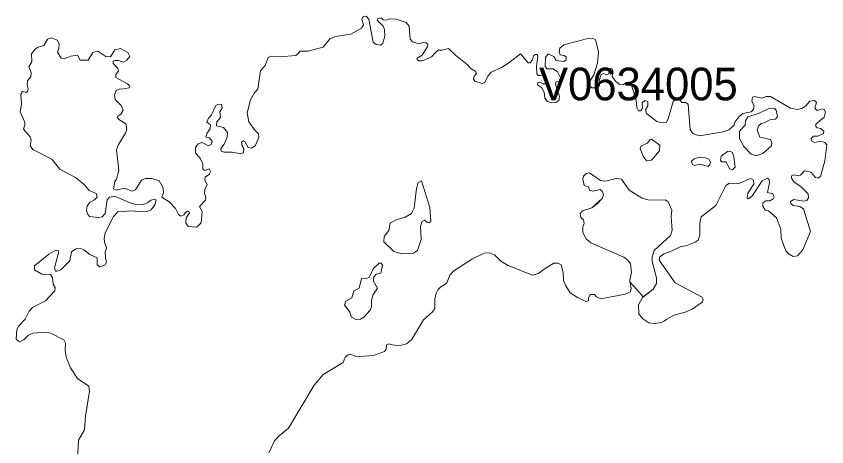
# Model space of a CAD drawing. Extents: x 369010 to 735936, y 6377141 to 6616555.
# Drawn here: x 451878 to 454365, y 6480290 to 6481609 of the extents above; entities that cross this region are included whole.
import ezdxf
from ezdxf.enums import TextEntityAlignment as Align

# ---------------------------------------------------------------- set-up
doc = ezdxf.new("R2010")
doc.units = 0
doc.header["$LTSCALE"] = 40
doc.layers.add('3', color=7, linetype='Continuous', lineweight=13)
doc.layers.add('4', color=7, linetype='Continuous')

msp = doc.modelspace()

# ---------------------------------------------------------------- linework, layer by layer
at = {"layer": '3'}
for points in [[(452404.03, 6481012.12), (452408.33, 6481011.3), (452409.49, 6481006.33), (452399.4, 6480991.44), (452398.4, 6480975.71), (452406.35, 6480964.96), (452432, 6480962.31), (452445.41, 6480976.54), (452448.88, 6481010.97), (452440.77, 6481025.86), (452459.14, 6481045.06), (452459.97, 6481054.99), (452455.83, 6481065.75), (452456.99, 6481078.82), (452463.78, 6481092.56), (452457.49, 6481107.45), (452458.31, 6481115.9), (452471.72, 6481124.83), (452474.04, 6481133.6), (452470.56, 6481141.22), (452456, 6481136.25), (452451.03, 6481141.55), (452451.03, 6481156.94), (452442.26, 6481173.82), (452428.36, 6481189.88), (452428.69, 6481207.09), (452436.47, 6481217.85), (452448.72, 6481222.81), (452467.91, 6481211.72), (452477.35, 6481217.02), (452479.5, 6481225.96), (452471.06, 6481236.22), (452460.3, 6481238.86), (452463.11, 6481250.12), (452473.38, 6481263.86), (452474.87, 6481276.43), (452463.11, 6481284.54), (452468.08, 6481296.46), (452477.18, 6481307.05), (452490.59, 6481335.85), (452498.37, 6481339.66), (452508.63, 6481338.5), (452509.79, 6481328.24), (452503.33, 6481316.32), (452505.15, 6481298.78), (452493.73, 6481286.03), (452492.91, 6481272.96), (452514.42, 6481267.99), (452526.67, 6481252.77), (452525.84, 6481238.2), (452516.74, 6481217.51), (452505.98, 6481204.44), (452507.14, 6481195.67), (452516.24, 6481193.02), (452540.74, 6481192.52), (452567.22, 6481187.56), (452575.99, 6481191.03), (452576.32, 6481203.61), (452571.19, 6481211.72), (452569.7, 6481223.14), (452574.33, 6481227.11), (452579.3, 6481225.13), (452590.39, 6481206.76), (452599.99, 6481204.77), (452611.57, 6481211.72), (452622.99, 6481237.38), (452621.5, 6481248.46), (452609.59, 6481260.71), (452592.37, 6481285.37), (452586.58, 6481313.18), (452597.17, 6481353.06), (452608.92, 6481374.58), (452619.35, 6481385.67), (452627.46, 6481441.61), (452642.19, 6481458.49), (452651.29, 6481482.65), (452660.89, 6481487.12), (452687.7, 6481484.8), (452736.03, 6481488.78), (452743.81, 6481495.23), (452748.11, 6481502.51), (452773.27, 6481502.51), (452819.61, 6481514.76), (452841.95, 6481541.24), (452858.5, 6481547.36), (452905.34, 6481554.65), (452937.78, 6481572.52), (452943.24, 6481582.62), (452938.94, 6481599), (452942.41, 6481608.6), (452952.18, 6481609.43), (452960.29, 6481600.49), (452973.69, 6481530.15), (452982.14, 6481522.37), (452996.2, 6481520.88), (453003.15, 6481527.34), (453008.95, 6481548.03), (453008.12, 6481568.38), (453004.31, 6481579.14), (452985.61, 6481597.84)], [(452985.61, 6481597.84), (452987.43, 6481602.81), (452997.86, 6481604.79), (453004.31, 6481598.34), (453014.57, 6481597.18), (453023.84, 6481600.99), (453044.2, 6481600.16), (453074.82, 6481590.56), (453083.75, 6481579.14), (453086.4, 6481539.59), (453093.68, 6481531.14), (453114.87, 6481525.02), (453126.29, 6481528.99), (453135.89, 6481528.17), (453140.85, 6481523.2), (453140.52, 6481517.08), (453123.97, 6481489.77), (453108.25, 6481480.67), (453108.08, 6481476.36), (453113.55, 6481472.23), (453124.14, 6481472.23), (453152.11, 6481485.3), (453165.18, 6481499.37), (453172.8, 6481505.49), (453185.54, 6481505.16), (453204.57, 6481510.46), (453226.42, 6481489.77), (453262.17, 6481461.8), (453274.42, 6481448.06), (453286.66, 6481441.11), (453290.8, 6481433.83), (453282.86, 6481425.39), (453280.87, 6481416.29), (453285.67, 6481410.49), (453307.85, 6481402.88), (453315.46, 6481406.69), (453325.06, 6481425.88), (453335.49, 6481438.13), (453366.93, 6481452.7), (453389.27, 6481466.93), (453425.69, 6481493.74), (453449.02, 6481466.43), (453455.15, 6481466.43), (453462.1, 6481475.7), (453465.57, 6481488.28), (453470.7, 6481492.58), (453476.83, 6481491.75), (453478.65, 6481486.46), (453474.51, 6481456.83), (453475.17, 6481432.34), (453479.14, 6481427.7), (453485.6, 6481427.37), (453493.21, 6481429.69), (453503.14, 6481423.24), (453506.29, 6481407.84), (453501.32, 6481401.72), (453494.87, 6481402.55), (453484.44, 6481407.02), (453478.32, 6481406.35), (453477.16, 6481399.07), (453489.74, 6481390.63), (453497.51, 6481376.4), (453500.16, 6481358.03), (453507.78, 6481347.77), (453520.52, 6481343.79), (453533.43, 6481344.62), (453542.7, 6481351.57), (453544.52, 6481363.82), (453532.27, 6481400.89), (453534.59, 6481407.84), (453545.01, 6481409.83), (453548.49, 6481420.42), (453538.39, 6481439.29), (453525.48, 6481448.06), (453506.29, 6481448.06), (453501.32, 6481456.5), (453501.65, 6481482.98), (453510.42, 6481494.07), (453527.8, 6481485.63), (453534.26, 6481473.71), (453557.92, 6481470.24), (453565.21, 6481475.7), (453565.21, 6481485.3), (453559.58, 6481489.11), (453546.83, 6481490.6), (453543.86, 6481499.86), (453546.5, 6481511.62), (453558.75, 6481522.04), (453627.93, 6481540.41), (453645.14, 6481541.9), (453655.9, 6481538.43), (453664.34, 6481500.2), (453661.2, 6481465.77), (453650.11, 6481429.36), (453634.55, 6481405.2), (453636.21, 6481397.09), (453644.48, 6481390.3), (453656.89, 6481389.8), (453667.49, 6481395.93), (453668.65, 6481404.04)], [(452102.48, 6481075.35), (452085.77, 6481094.55), (452060.44, 6481115.23), (452012.61, 6481140.89), (451987.29, 6481171.01), (451929.7, 6481200.96), (451921.25, 6481212.38), (451923.9, 6481230.09), (451921.59, 6481240.02), (451900.57, 6481263.03), (451904.54, 6481276.77), (451904.7, 6481284.54), (451890.47, 6481316.32), (451894.28, 6481339.33), (451892.62, 6481370.61), (451897.59, 6481378.38), (451909.5, 6481376.07), (451914.14, 6481381.03), (451915.3, 6481386.33), (451911.49, 6481398.25), (451912.65, 6481412.81), (451923.08, 6481423.24), (451924.73, 6481436.64), (451917.45, 6481454.52), (451926.22, 6481469.58), (451925.39, 6481493.74), (451937.31, 6481508.97), (451946.08, 6481514.76), (451962.63, 6481519.73), (451974.88, 6481538.92), (451986.3, 6481543.06), (452004.34, 6481535.78), (452009.8, 6481524.69), (452009.3, 6481510.13), (452005.5, 6481499.37), (452016.25, 6481480.67), (452025.69, 6481478.35), (452045.55, 6481486.79), (452065.9, 6481489.77), (452074.68, 6481474.87), (452098.84, 6481475.2), (452113.74, 6481498.71), (452128.96, 6481502.51), (452153.29, 6481485.63), (452167.52, 6481484.47), (452180.6, 6481505.99), (452197.81, 6481510.13), (452220.82, 6481497.88), (452226.94, 6481486.46), (452217.34, 6481474.54), (452206.25, 6481468.42), (452192.52, 6481473.38), (452180.93, 6481473.71), (452175.63, 6481471.4), (452175.97, 6481464.12), (452189.7, 6481449.55), (452192.52, 6481440.78), (452184.07, 6481430.85), (452184.41, 6481422.08), (452219.33, 6481402.55), (452225.78, 6481395.93), (452224.62, 6481390.3), (452202.78, 6481385.67), (452195.83, 6481386.83), (452184.74, 6481381.36), (452179.94, 6481367.63), (452181.59, 6481354.22), (452199.96, 6481336.18), (452206.09, 6481321.62), (452199.14, 6481308.71), (452189.87, 6481303.25), (452188.87, 6481298.28), (452196.49, 6481290.67), (452214.53, 6481279.08), (452217.84, 6481261.87), (452213.37, 6481250.45), (452192.02, 6481216.69), (452185.56, 6481200.3), (452192.85, 6481136.58), (452186.06, 6481110.27), (452181.1, 6481102.99), (452176.46, 6481080.31), (452185.4, 6481076.17), (452210.56, 6481082.3), (452234.39, 6481072.7), (452243.99, 6481077.17), (452262.36, 6481106.79), (452274.61, 6481112.09), (452294.63, 6481111.76), (452316.48, 6481104.81), (452329.55, 6481083.46), (452330.71, 6481066.58), (452324.59, 6481054.99), (452347.26, 6481040.09), (452366.96, 6481020.23), (452376.06, 6481001.86), (452383.01, 6480996.73), (452392.11, 6481000.21), (452396.42, 6481007.16), (452404.03, 6481012.12)], [(453668.65, 6481404.04), (453667.16, 6481412.81), (453672.45, 6481430.52), (453679.07, 6481433.5), (453690.49, 6481429.36), (453695.95, 6481432.34), (453698.6, 6481447.73), (453705.39, 6481449.55), (453708.53, 6481442.27), (453706.55, 6481425.06), (453716.64, 6481410.49), (453729.22, 6481399.73), (453739.48, 6481399.07), (453747.43, 6481404.7), (453765.47, 6481398.58), (453780.36, 6481352.23), (453781.85, 6481329.23), (453787.64, 6481319.3), (453794.93, 6481318.97), (453799.56, 6481327.41), (453799.06, 6481343.79), (453806.84, 6481350.75), (453815.94, 6481348.43), (453815.61, 6481334.36), (453809.16, 6481322.78), (453811.81, 6481310.86), (453843.25, 6481287.19), (453859.8, 6481282.89), (453872.55, 6481283.72), (453878.67, 6481295.3), (453893.9, 6481347.77), (453899.69, 6481355.38), (453911.11, 6481358.03), (453920.05, 6481344.62), (453931.13, 6481344.95), (453939.58, 6481339.33), (453946.03, 6481261.04), (453954.14, 6481249.95), (453974, 6481242.67), (454047.48, 6481254.59), (454064.2, 6481261.04), (454080.59, 6481275.61), (454082.9, 6481284.87), (454094.82, 6481301.43), (454107.4, 6481310.86), (454132.72, 6481316.65), (454140.5, 6481324.76), (454142.65, 6481335.52), (454134.87, 6481348.92), (454137.52, 6481361.5), (454144.47, 6481363.82), (454165.16, 6481358.36), (454178.56, 6481363.82), (454192.63, 6481362.99), (454253.54, 6481327.41), (454275.05, 6481323.6), (454290.61, 6481327.74), (454300.87, 6481334.69), (454312.46, 6481349.26), (454327.35, 6481350.75), (454333.48, 6481344.62), (454328.18, 6481327.41), (454333.14, 6481320.95), (454340.43, 6481320.95), (454351.02, 6481325.92), (454356.81, 6481323.93), (454360.62, 6481316.32), (454356.48, 6481300.27), (454331.49, 6481278.75), (454331.49, 6481271.8), (454335.46, 6481266.83), (454346.88, 6481265.68), (454356.15, 6481256.9), (454355.32, 6481249.62), (454337.61, 6481241.51), (454324.21, 6481241.51), (454317.42, 6481234.73), (454317.75, 6481227.44), (454327.35, 6481222.81), (454348.04, 6481226.62), (454359.13, 6481222.81), (454364.92, 6481215.2), (454358.63, 6481166.04), (454345.89, 6481117.88), (454337.45, 6481113.25), (454329.83, 6481114.74), (454315.6, 6481131.62), (454296.57, 6481135.42), (454284.32, 6481122.02), (454278.86, 6481120.53), (454264.29, 6481123.51), (454256.68, 6481120.2), (454256.35, 6481113.25), (454264.29, 6481101.66), (454285.98, 6481086.44), (454307.49, 6481064.59), (454309.31, 6481052.67), (454304.02, 6481044.73), (454294.09, 6481042.74), (454263.8, 6481047.71)], [(454263.8, 6481047.71), (454253.37, 6481041.91), (454254.53, 6481033.97), (454262.64, 6481029.01), (454282.5, 6481026.19), (454293.59, 6481018.91), (454314.94, 6480949.23), (454291.44, 6480893.79), (454274.89, 6480874.92), (454261.48, 6480873.1), (454249.23, 6480879.56), (454238.81, 6480889.82), (454225.4, 6480929.04), (454223.91, 6480956.51), (454210.17, 6480991.44), (454186.34, 6481012.46), (454175.58, 6481015.1), (454168.3, 6481027.02), (454168.8, 6481037.45), (454178.4, 6481043.57), (454189.82, 6481043.57), (454200.91, 6481049.69), (454203.55, 6481056.15), (454199.75, 6481065.42), (454183.36, 6481068.73), (454188.99, 6481100.17), (454188.66, 6481109.11), (454182.87, 6481113.25), (454167.14, 6481105.14), (454137.02, 6481059.62), (454125.11, 6481050.02), (454120.47, 6481052.67), (454122.46, 6481066.08), (454140.83, 6481095.54), (454140, 6481106.79), (454130.9, 6481112.09), (454092.67, 6481095.21), (454066.35, 6481097.52), (454054.77, 6481090.24), (454024.98, 6481029.34), (453979.13, 6480994.42), (453974.99, 6480975.38), (453975.66, 6480938.14), (453970.69, 6480922.92), (453961.09, 6480916.3), (453935.77, 6480906.7), (453914.75, 6480902.56), (453890.42, 6480889.82), (453864.77, 6480880.71), (453852.52, 6480872.27), (453851.03, 6480861.18), (453900.02, 6480792.17), (453982.94, 6480748.15), (453985.25, 6480739.7), (453982.94, 6480733.25), (453951.49, 6480711.4), (453930.47, 6480701.8), (453897.21, 6480692.54), (453874.37, 6480681.12), (453866.59, 6480675.99), (453857.98, 6480670.36), (453836.8, 6480667.38), (453819.25, 6480670.03), (453800.88, 6480681.45), (453788.64, 6480696.84), (453787.81, 6480724.31), (453799.23, 6480746.99), (453802.21, 6480749.3), (453831.83, 6480772.64), (453842.42, 6480790.35), (453842.42, 6480807.89), (453829.68, 6480857.71), (453829.68, 6480871.94), (453835.14, 6480890.98), (453885.79, 6480936.99), (453890.42, 6480953.54), (453887.44, 6480994.08), (453890.09, 6481014.44), (453878.84, 6481040.76), (453869.57, 6481046.55), (453820.25, 6481045.89), (453798.4, 6481051.18), (453759.01, 6481076.01), (453735.01, 6481109.77), (453718.46, 6481112.09), (453687.02, 6481103.65), (453670.63, 6481105.97), (453637.03, 6481128.97), (453626.28, 6481127.81), (453618.33, 6481119.04), (453616.84, 6481109.44), (453620.65, 6481090.57), (453634.39, 6481086.77), (453636.7, 6481076.51), (453647.79, 6481072.7), (453669.31, 6481077.99), (453676.59, 6481071.87), (453679.57, 6481060.78), (453675.76, 6481050.36), (453661.2, 6481035.79)], [(452066.4, 6480252.46), (452069.22, 6480309.56), (452088.08, 6480341.67), (452090.73, 6480383.87), (452103.47, 6480460.5), (452101.32, 6480475.06), (452066.73, 6480499.06), (452045.22, 6480532), (452032.14, 6480564.6), (452028.34, 6480585.29), (452029.83, 6480607.47), (452024.53, 6480617.89), (451984.97, 6480638.25), (451966.93, 6480640.57), (451930.03, 6480637.75), (451915.79, 6480631.3), (451901.72, 6480617.07), (451888.98, 6480611.44), (451878.39, 6480619.05), (451879.88, 6480649.34), (451886, 6480660.76), (451906.36, 6480680.79), (451918.61, 6480705.28), (451928.54, 6480716.37), (451968.26, 6480736.56), (451997.22, 6480767.67), (451998.05, 6480777.61), (451991.59, 6480788.03), (451989.94, 6480808.72), (451983.48, 6480817.49), (451956.67, 6480818.98), (451934.49, 6480832.39), (451934.49, 6480844.63), (451978.68, 6480880.22), (452000.2, 6480892.13), (452006.65, 6480890.98), (452008.14, 6480883.69), (451995.9, 6480838.18), (451998.54, 6480827.75), (452004.34, 6480827.42), (452015.76, 6480832.06), (452042.57, 6480859.7), (452048.36, 6480887.5), (452061.11, 6480895.94), (452075.67, 6480897.1), (452086.26, 6480892.96), (452104.47, 6480879.22), (452127.14, 6480868.8), (452126.81, 6480846.95), (452134.75, 6480841.16), (452150.48, 6480846.62), (452155.11, 6480855.39), (452151.97, 6480869.13), (452150.81, 6480886.01), (452155.11, 6480899.09), (452148.99, 6480917.12), (452148.16, 6480927.88), (452150.81, 6480945.43), (452176.46, 6480995.24), (452190.2, 6481009.81), (452231.41, 6481012.95), (452268.32, 6481009.48), (452280.07, 6481011.3), (452292.81, 6481015.93), (452303.24, 6481031.65), (452307.54, 6481046.22), (452302.58, 6481048.87), (452291.82, 6481045.39), (452281.56, 6481036.95), (452264.68, 6481030.83), (452245.48, 6481031.98), (452224.95, 6481038.6), (452181.26, 6481057.64), (452164.88, 6481054.99), (452157.59, 6481046.55), (452151.47, 6481004.84), (452141.87, 6480994.91), (452131.11, 6480992.1), (452103.47, 6480995.57), (452097.35, 6481004.01), (452094.37, 6481015.1), (452096.36, 6481027.35), (452103.97, 6481039.27), (452118.54, 6481046.55), (452126.98, 6481054.66), (452124.16, 6481066.08), (452102.48, 6481075.35)], [(453661.2, 6481035.79), (453644.32, 6481022.05), (453616.02, 6481012.79), (453607.91, 6481004.51), (453610.06, 6480992.1), (453618.17, 6480985.31), (453620.48, 6480974.22), (453616.51, 6480964.13), (453616.18, 6480946.58), (453626.94, 6480926.72), (453640.68, 6480914.81), (453742.79, 6480870.78), (453755.04, 6480861.18), (453762.32, 6480850.1), (453765.47, 6480823.95), (453760.5, 6480799.78), (453761.16, 6480795.81), (453764.97, 6480774.96), (453762.32, 6480765.03), (453746.1, 6480756.92), (453671.29, 6480742.85), (453658.55, 6480749.3), (453652.1, 6480756.26), (453639.35, 6480756.59), (453634.39, 6480744.67), (453634.06, 6480736.56), (453625.61, 6480734.41), (453600.62, 6480746.99), (453577.78, 6480761.88), (453564.38, 6480783.07), (453557.1, 6480799.12), (453556.6, 6480823.62), (453550.48, 6480846.95), (453540.21, 6480852.74), (453527.47, 6480852.74), (453497.51, 6480833.88), (453480.63, 6480820.97), (453462.26, 6480816), (453387.79, 6480845.13), (453365.44, 6480858.87), (453345.58, 6480878.4), (453330.69, 6480884.19), (453314.14, 6480883.03), (453278.39, 6480866.15), (453221.29, 6480829.41), (453208.21, 6480815.17), (453199.77, 6480792.5), (453193.65, 6480786.87), (453180.57, 6480780.25), (453171.64, 6480771.15), (453166.84, 6480760.72), (453162.37, 6480742.02), (453162.7, 6480713.22), (453155.42, 6480702.96), (453127.28, 6480678.8), (453090.54, 6480617.89), (453075.15, 6480605.65), (453051.81, 6480599.19), (453031.62, 6480601.84), (453021.03, 6480605.65), (453014.74, 6480602.17), (453013.25, 6480588.77), (453008.12, 6480581.15), (452974.36, 6480569.57), (452932.98, 6480566.26), (452918.09, 6480567.75), (452905.01, 6480573.04), (452896.74, 6480571.55), (452887.47, 6480563.94), (452881.01, 6480548.22), (452819.61, 6480510.98), (452792.63, 6480478.54), (452713.52, 6480347.13), (452685.22, 6480323.3), (452670.33, 6480307.9), (452653.28, 6480270.83)]]:
    msp.add_lwpolyline(points, dxfattribs=at)
for points in [[(454188.82, 6481327.74), (454157.38, 6481312.51), (454122.29, 6481301.43), (454115.34, 6481289.01), (454114.51, 6481275.28), (454097.63, 6481256.57), (454097.63, 6481234.73), (454110.38, 6481210.56), (454132.88, 6481186.4), (454148.61, 6481181.1), (454168.96, 6481188.39), (454195.44, 6481212.05), (454196.6, 6481221.65), (454191.97, 6481231.58), (454159.7, 6481238.2), (454151.75, 6481260.05), (454155.23, 6481273.79), (454163.17, 6481280.24), (454173.1, 6481282.23), (454190.48, 6481292.16), (454208.02, 6481294.14), (454214.15, 6481301.76), (454209.51, 6481321.62), (454204.22, 6481326.58)], [(453827.2, 6481232.08), (453822.73, 6481231.25), (453814.62, 6481220.16), (453795.09, 6481212.05), (453792.44, 6481204.11), (453802.04, 6481180.61), (453811.97, 6481166.54), (453827.69, 6481167.7), (453852.19, 6481196.83), (453852.52, 6481214.37)], [(454075.29, 6481138.07), (454083.73, 6481147.01), (454080.25, 6481177.63), (454075.29, 6481191.37), (454067.18, 6481196), (454060.39, 6481194.84), (454041.2, 6481180.61), (454038.55, 6481168.36), (454042.35, 6481163.39), (454056.09, 6481163.39), (454066.02, 6481141.88)], [(453974.5, 6481177.13), (453958.11, 6481172.66), (453950, 6481164.88), (453952.32, 6481155.78), (453959.6, 6481152.31), (453976.48, 6481155.78), (454000.65, 6481148.83), (454006.27, 6481153.8), (454007.93, 6481161.91), (454002.96, 6481171.5), (453991.05, 6481176.8)], [(453616.51, 6480964.13), (453616.18, 6480946.58), (453626.94, 6480926.72), (453640.68, 6480914.81), (453742.79, 6480870.78), (453755.04, 6480861.18), (453762.32, 6480850.1), (453765.47, 6480823.95), (453760.5, 6480799.78), (453761.16, 6480795.65), (453782.51, 6480771.65), (453802.04, 6480749.3), (453831.83, 6480772.64), (453842.42, 6480790.35), (453842.42, 6480807.89), (453829.68, 6480857.71), (453829.68, 6480871.94), (453835.14, 6480890.98), (453885.79, 6480936.99), (453890.42, 6480953.54), (453887.44, 6480994.08), (453890.09, 6481014.44), (453878.84, 6481040.76), (453869.57, 6481046.55), (453820.25, 6481045.89), (453798.4, 6481051.18), (453759.01, 6481076.01), (453735.01, 6481109.77), (453718.46, 6481112.09), (453687.02, 6481103.65), (453670.63, 6481105.97), (453637.03, 6481128.97), (453626.28, 6481127.81), (453618.33, 6481119.04), (453616.84, 6481109.44), (453620.65, 6481090.57), (453634.39, 6481086.77), (453636.7, 6481076.51), (453647.79, 6481072.7), (453669.31, 6481077.99), (453676.59, 6481071.87), (453679.57, 6481060.78), (453675.76, 6481050.36), (453644.32, 6481022.05), (453616.02, 6481012.79), (453607.91, 6481004.51), (453610.06, 6480992.1), (453618.17, 6480985.31), (453620.48, 6480974.22)], [(453121.65, 6481104.48), (453111.23, 6481099.84), (453106.1, 6481081.14), (453099.48, 6481020.56), (453090.71, 6481004.84), (453071.84, 6480993.75), (453044.36, 6480985.31), (453025.5, 6480974.89), (453021.86, 6480952.71), (453006.96, 6480934.34), (453006.13, 6480917.46), (453037.25, 6480888.33), (453061.41, 6480881.05), (453096.99, 6480883.03), (453109.57, 6480891.47), (453120.66, 6480924.74), (453119.01, 6480964.62), (453123.64, 6480979.85), (453130.59, 6480983.82), (453139.69, 6480976.87), (453146.65, 6480976.54), (453150.78, 6480982.17), (453147.31, 6481022.88)], [(452998.02, 6480852.41), (452991.57, 6480851.92), (452973.2, 6480834.7), (452960.79, 6480808.22), (452949.37, 6480804.42), (452937.12, 6480805.24), (452930.17, 6480776.12), (452914.44, 6480768.01), (452908.32, 6480745.83), (452889.62, 6480735.57), (452885.81, 6480723.98), (452901.04, 6480704.45), (452906.5, 6480686.91), (452919.91, 6480679.63), (452934.47, 6480681.12), (452944.73, 6480687.24), (452964.59, 6480708.26), (452968.73, 6480719.35), (452968.23, 6480737.06), (452972.04, 6480754.6), (452986.27, 6480776.12), (452974.36, 6480796.8), (452975.51, 6480810.21), (452982.47, 6480818.65), (452996.7, 6480822.13), (453001.83, 6480846.62)]]:
    msp.add_lwpolyline(points, close=True, dxfattribs=at)

# ---------------------------------------------------------------- texts
at = {"layer": '4'}
msp.add_text('V0634005', height=100, dxfattribs=at).set_placement((453786.97, 6481351.71), align=Align.CENTER)

doc.saveas('drawing.dxf')
